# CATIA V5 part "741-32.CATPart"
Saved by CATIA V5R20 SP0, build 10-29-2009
Part number: 741-32
Bounding box of the stored display mesh (mm): x -28 to 28, y -28 to 28, z -30 to 45
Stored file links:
  C:\Users\Utente\Desktop\IO LAVORO\3D X SITO CF\X SITO\741\741-32.CATPart
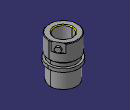
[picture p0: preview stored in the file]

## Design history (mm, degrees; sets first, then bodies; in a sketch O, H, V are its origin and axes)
Set1
  DatumSurface1 to DatumSurface42 "741-32"
Body1 (main body)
